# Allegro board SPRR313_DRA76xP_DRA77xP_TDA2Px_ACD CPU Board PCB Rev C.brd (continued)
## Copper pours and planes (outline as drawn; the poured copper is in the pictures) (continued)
VBUS_USB1 on L12-SIGNAL: 35.69,169.67 42.42,169.67 44.96,172.21 44.96,179.2 44.58,179.58 0.64,179.58 0.64,85.47 5.21,85.47 8.13,88.39 8.13,91.31 5.08,94.36 5.08,160.02 4.7,160.4 4.7,162.81 7.87,165.99 12.45,165.99 15.11,163.32 29.34,163.32
VBUS_USB2 on TOP: 35.69,167.77 35.43,167.51 35.43,165.48 35.69,165.23 37.72,165.23 37.97,165.48 37.97,166.88 37.08,167.77
VBUS_USB2 on L12-SIGNAL: 81.79,179.32 46.99,179.32 46.99,172.97 43.05,169.04 36.58,169.04 35.05,167.51 35.05,165.23 36.7,163.58 61.59,163.58 66.55,168.53 77.34,168.53 81.79,172.97
VCC_1V1USB on TOP: 45.09,114.3 47.88,114.3 48.26,114.68 48.26,115.95 48.01,116.2 45.59,116.2 44.96,115.57 44.96,114.43
VCC_1V1USB on L3-SIGNAL: 44.7,113.79 53.85,113.79 58.29,118.24 58.29,124.84 56.01,127.13 47.62,127.13 45.47,124.97 45.47,121.16 44.07,119.76 44.07,114.43
VCC_1V1VIDEO on TOP: 45.72,111.25 46.23,111.25 46.74,111.76 46.74,113.67 46.48,113.92 45.34,113.92 44.96,113.54 44.96,112.01
VCC_1V1VIDEO on BOTTOM: 31.62,103.5 31.37,103.5 31.37,104.65 31.75,105.03 31.75,110.36 32.13,110.74 33.4,110.74 34.42,109.73 34.42,105.16 33.15,103.89 32.13,103.89 32.13,103.5 31.88,103.5 31.88,104.14 31.62,104.14
VCC_1V1VIDEO on L3-SIGNAL: 31.37,103.89 31.37,112.78 34.92,116.33 34.92,126.87 34.54,127.25 24.77,127.25 23.11,125.6 18.54,125.6 17.53,126.62 17.53,131.7 19.56,133.73 34.67,133.73 40.13,128.27 40.13,108.84 34.67,103.38 31.88,103.38
VCC_1V1VIDEO on L5-SIGNAL: 31.37,113.54 45.34,113.54 46.61,112.27 46.61,105.79 42.8,101.98 32.51,101.98 30.1,104.39 30.1,112.27
VCC_CSI2_IO on L7-SIGNAL: 26.67,40.39 26.67,32.13 19.81,25.27 17.78,25.27 16.76,26.29 16.76,31.62 22.61,37.47 22.61,39.88 23.62,40.89 26.16,40.89
VCC_VTERM on L12-SIGNAL: 36.07,122.81 36.07,116.59 36.58,116.08 38.35,116.08 39.37,117.09 39.37,123.06 38.86,123.57 36.83,123.57
VDD18_DISP1 on L7-SIGNAL: 18.16,113.92 34.16,113.92 37.08,116.84 37.08,127.51 33.53,131.06 19.3,131.06 15.24,127 15.24,116.84
VDD_CDCEL925 on TOP: 50.55,51.69 50.55,48.01 50.93,47.62 50.93,46.86 50.67,46.61 47.62,46.61 46.48,47.75 46.48,53.34 47.12,53.98 48.01,53.98 48.64,53.34 48.64,52.45 49.02,52.07 50.16,52.07
VDD_CDCM9102 on L14-SIGNAL: 33.27,153.42 32.89,153.8 30.61,153.8 27.18,150.37 27.18,146.05 27.81,145.41 32,145.41 33.27,146.69
VDD_CORE_APM on TOP: 173.86,74.8 173.1,75.56 173.1,79.76 173.74,80.39 173.74,81.53 178.69,81.53 178.82,81.41 178.82,79.28 178.17,78.63 178.17,71.93 177.23,70.99 173.86,70.99
VDD_CORE_AVS on TOP: 178.69,82.04 175.01,82.04 175.01,84.07 178.69,84.07
VDD_CORE_AVS on L8-PWR1: 87.63,51.28 88.9,51.28 89.66,50.52 93.34,50.52 94.11,51.28 94.49,51.28 94.49,55.98 95,55.98 95.12,56.11 96.14,56.11 96.9,55.35 97.66,55.35 97.79,55.47 97.79,56.87 97.16,57.51 96.39,57.51 95.76,56.87 94.49,56.87 94.49,61.32 95.12,61.95 96.27,61.95 97.16,61.06 97.66,61.06 98.3,61.7 98.3,62.2 98.93,62.84 99.57,62.84 105.49,68.76 105.49,69.47 107.38,71.37 112.52,71.37 112.52,71.36 156.97,71.36 156.98,71.37 157.35,71.37 158.62,72.64 160.4,72.64 160.78,73.03 168.66,73.03 169.8,71.88 177.55,71.88 178.69,73.03 178.69,83.82 177.8,84.71 103.78,84.71 92.58,73.51 92.58,68.05 91.06,66.52 91.06,62.97 90.3,62.2 89.03,62.2 89,62.23 88.14,62.23 87.76,61.85 87.76,57.28 89.66,57.28 89.66,55.37 89.15,54.86 89.15,54.61 89.28,54.48 89.28,53.7 89.03,53.44 87.63,53.44
VDD_CORE_AVS on L12-SIGNAL: 85.72,48.87 85.72,52.58 90.04,56.9 90.04,60.43 95.12,60.43 96.14,59.41 96.14,49.12 95.89,48.87
VDD_CORE_SW3 on TOP: 166.75,72.01 168.4,72.01 168.53,72.14 169.04,72.14 170.05,71.12 172.34,71.12 172.34,73.91 168.28,73.91 167.89,73.53 167.89,72.52 167.77,72.39 166.75,72.39
VDD_DSPEVE_APM on TOP: 149.1,61.21 149.1,78.17 150.43,79.5 154.18,79.5 154.18,69.47 154.43,69.22 154.43,61.47 153.92,60.96 149.35,60.96
VDD_DSPEVE_AVS on TOP: 148.84,65.28 146.81,65.28 146.81,69.22 148.84,69.22
VDD_DSPEVE_AVS on L3-SIGNAL: 94.74,57 95.5,57 95.52,57.01 95.63,56.9 98.78,56.9 99.19,56.49 147.07,56.49 149.22,58.65 149.22,65.84 149.19,65.87 149.19,68.24 149.16,68.26 149.16,69.79 148.08,70.87 141.05,70.87 139.95,69.77 97.71,69.77 94.61,66.67 94.61,57.12
VDD_DSPEVE_AVS on L8-PWR1: 94.74,57 95.5,57 96.52,58.01 97.66,58.01 99.19,56.49 116.08,56.49 117.75,58.17 139.95,58.17 140.84,59.05 143.89,59.05 146.18,61.34 149.22,61.34 149.22,69.72 149.1,69.85 108.71,69.85 104.78,65.91 104.78,65.02 103.75,64 101.73,63.98 99.69,61.95 99.19,61.95 98.04,60.81 96.9,60.81 96.27,61.44 95,61.44 94.61,61.06 94.61,57.12
VDD_DSPEVE_SW1 on TOP: 160.53,69.85 155.45,69.85 154.81,69.22 154.81,66.04 155.07,65.79 157.35,65.79 157.86,66.29 157.86,68.2 159.13,69.47 159.64,69.47 159.77,69.6 160.53,69.6
VDD_DSPEVE_SW2 on TOP: 160.53,70.1 155.57,70.1 154.81,70.87 154.81,73.91 155.07,74.17 157.35,74.17 158.37,73.15 158.37,70.87 158.62,70.61 158.75,70.61 158.88,70.48 159.51,70.48 159.64,70.36 160.53,70.36
VDD_GPU_APM on TOP: 135.51,68.58 134.87,67.94 134.87,65.79 137.16,65.79 137.41,66.04 137.67,66.04 137.92,65.79 140.34,65.79 140.34,67.82 139.57,68.58 139.57,70.61 139.19,70.99 135.89,70.99 135.51,70.61
VDD_GPU_AVS on TOP: 135.89,71.25 139.19,71.25 139.19,73.66 138.94,73.91 136.14,73.91 135.89,73.66
VDD_GPU_AVS on L3-SIGNAL: 89.03,56.62 93.57,56.62 94.11,57.15 94.11,67.06 97.41,70.36 139.45,70.36 141.86,72.77 141.86,78.74 137.57,83.03 96.65,83.03 96.52,83.16 88.52,83.16 82.3,76.94 82.3,59.18 84.84,56.64 89.03,56.64
VDD_GPU_AVS on L9-PWR2: 89.03,56.62 90.93,56.62 91.19,56.87 91.19,57.89 91.88,58.59 93.15,58.59 93.34,58.78 93.34,61.32 93.22,61.44 93.22,61.57 92.08,62.71 92.08,67.03 95,69.95 95,70.48 96.62,72.11 135.89,72.11 135.89,72.14 139.19,72.14 139.57,72.52 139.57,78.11 138.81,78.87 136.37,78.87 131.93,83.31 97.41,83.31 97.4,83.3 91.55,83.3 91.29,83.57 82.17,83.57 77.09,78.49 77.09,62.48 77.62,61.95 87,61.95 87.5,61.44 87.5,60.81 88.52,59.79 88.52,59.28 89.03,58.78
VDD_GPU_SW2 on TOP: 134.87,64.64 134.87,63.75 135.13,63.5 136.53,63.5 136.91,63.12 136.91,60.71 137.16,60.71 137.16,64.64
VDD_GPU_SW3 on TOP: 140.21,64.64 140.21,63.75 139.95,63.5 138.56,63.5 138.18,63.12 138.18,60.71 137.92,60.71 137.92,64.64
VDD_IVA_APM on TOP: 161.29,83.44 161.67,83.82 169.8,83.82 170.43,83.19 170.43,80.52 169.67,79.76 165.48,79.76 165.23,79.5 161.93,79.5 161.29,80.14
VDD_IVA_AVS on TOP: 165.35,84.2 162.18,84.2 162.18,86.23 165.35,86.23
VDD_IVA_AVS on L9-PWR2: 89.79,53.57 89.28,53.57 88.93,53.21 72.26,53.21 67.69,57.78 67.69,88.9 72.39,93.6 153.54,93.6 159,88.14 160.91,88.14 162.43,86.61 162.43,84.07 163.32,83.19 165.74,83.19 167,84.45 167,90.93 158.62,99.31 62.23,99.31 55.88,92.96 55.88,47.75 78.49,47.75 79.25,48.51 89.92,48.51 90.93,49.53 90.93,52.45 90.58,52.81 90.55,52.81
VDD_IVA_SW4 on TOP: 163.32,73.15 163.32,74.68 161.42,76.58 161.42,78.74 161.8,79.12 164.47,79.12 164.97,78.61 164.97,76.2 163.7,74.93 163.7,74.04 163.58,73.91 163.58,73.15
VDD_MPU_APM on TOP: 135.51,51.56 134.87,52.2 134.87,54.36 137.16,54.36 137.41,54.1 137.67,54.1 137.92,54.36 140.34,54.36 140.34,52.32 139.57,51.56 139.57,49.53 139.19,49.15 135.89,49.15 135.51,49.53
VDD_MPU_AVS on TOP: 135.89,48.9 139.19,48.9 139.19,46.48 138.94,46.23 136.14,46.23 135.89,46.48
VDD_MPU_AVS on L3-SIGNAL: 104.27,55.16 104.05,55.37 98.3,55.37 97.41,56.26 92.08,56.26 91.44,55.63 91.44,42.93 93.85,40.51 137.41,40.51 140.21,43.31 140.21,50.55 139.45,51.31 139.26,51.31 139.26,51.37 135.47,55.16
VDD_MPU_AVS on L8-PWR1: 94.74,51.28 97.05,51.28 101.73,46.61 103,46.61 103.25,46.35 106.3,46.35 107.95,44.7 116.33,44.7 116.4,44.77 117.03,44.77 117.47,45.21 121.79,45.21 122.43,44.58 125.86,44.58 126.36,45.09 127.76,45.09 128.4,44.45 134.37,44.45 135,45.09 136.53,45.09 136.91,44.7 137.54,44.7 139.57,46.74 139.57,49.28 139.19,49.66 139.19,50.55 139.7,51.05 139.7,54.48 139.03,55.16 104.08,55.16 104.01,55.09 97.92,55.09 97.79,54.97 96.9,54.97 96.01,55.85 95.25,55.85 94.74,55.35
VDD_MPU_SW0 on TOP: 134.87,55.5 134.87,56.39 135.13,56.64 136.53,56.64 136.91,57.02 136.91,59.44 137.16,59.44 137.16,55.5
VDD_MPU_SW1 on TOP: 140.21,55.5 140.21,56.39 139.95,56.64 138.56,56.64 138.18,57.02 138.18,59.44 137.92,59.44 137.92,55.5
VDD_SDIO_APM on TOP: 177.8,70.74 177.8,67.94 175.64,67.94 174.88,68.71 174.88,70.1 175.51,70.74
VDD_SDIO_APM on L7-SIGNAL: 174.62,70.61 174.62,68.33 175.77,67.18 181.61,67.18 183.26,65.53 189.23,65.53 189.99,66.29 189.99,70.48 188.09,72.39 179.71,72.39 179.07,71.75 175.77,71.75
VDD_SDIO_DV on TOP: 178.18,67.94 178.18,70.74 180.21,70.74 180.21,67.94
VDD_SDIO_DV on L8-PWR1: 88.52,62.59 90.3,62.59 90.68,62.97 90.68,66.65 91.95,67.92 91.95,73.79 92.08,73.79 103.38,85.09 178.31,85.09 179.2,84.2 179.2,71.75 178.56,71.12 178.56,68.58 179.45,67.69 182.12,67.69 183.07,68.64 183.07,84.65 179.58,88.14 99.34,88.14 87.76,76.56 87.76,63.35
VDD_SDIO_DV on L10-SIGNAL: 130.43,154.31 142.24,154.31 147.32,159.38 209.04,159.38 215.39,153.03 215.39,91.06 210.57,86.23 210.57,69.85 220.22,69.85 220.22,164.85 216.66,168.4 130.3,168.4 126.75,164.85 126.75,157.99
VDD_SDIO_DV on L12-SIGNAL: 178.18,70.87 178.18,66.04 180.09,64.14 209.93,64.14 211.58,65.79 211.58,71.75 210.57,72.77 180.09,72.77
VDDA_CDCM9102 on L14-SIGNAL: 21.21,148.72 21.21,151.76 20.7,152.27 20.7,154.31 22.35,155.96 26.8,155.96 28.19,154.56 28.19,152.02 27.43,151.26 23.62,151.26 22.99,150.62 22.99,148.84 22.61,148.46 21.46,148.46
VDDHA_DISP1 on L10-SIGNAL: 31.88,127 31.88,119.25 33.15,117.98 35.69,117.98 37.08,119.38 37.08,127.89 35.81,129.16 34.04,129.16
VDDHS_DISP1 on L14-SIGNAL: 21.59,127.51 21.59,117.86 22.48,116.97 27.56,116.97 27.94,117.35 27.94,125.35 25.02,128.27 22.35,128.27
VDDI_MMC2 on TOP: 146.05,133.22 146.43,133.22 146.86,133.65 146.86,134.04 146.94,134.11 146.94,134.75 145.92,133.73 145.92,133.35
VDDL_DISP1 on L14-SIGNAL: 26.04,129.41 26.04,128.14 28.45,125.73 28.45,117.47 27.94,116.97 27.94,116.46 28.45,115.95 30.48,115.95 31.88,117.35 31.88,127.76 29.59,130.05 26.67,130.05
VDDR_APM on BOTTOM: 142.37,25.91 137.41,30.86 137.41,34.92 139.83,37.34 139.83,38.48 139.45,38.86 137.16,38.86 137.16,42.55 137.54,42.93 141.6,42.93 143.13,41.4 143.13,28.45 143.51,28.07 145.03,28.07 145.41,28.45 145.41,29.08 145.8,29.46 146.05,29.46 147.96,27.56 147.96,25.78 147.7,25.78 147.7,26.8 146.43,26.8 146.3,26.92 143.51,26.92 143.51,19.05 143.76,18.8 146.18,18.8 147.7,17.27 152.15,17.27 152.53,17.65 152.53,18.29 152.91,18.67 155.07,18.67 155.19,18.54 155.19,15.37 154.31,14.48 142.75,14.48 142.37,14.86
VDDR_MEM_1V35 on BOTTOM: 142.24,13.97 145.41,13.97 145.41,11.94 142.24,11.94
VDDR_MEM_1V35 on L8-PWR1: 55.24,10.79 55.24,33.4 55.26,33.39 140.73,33.39 141.48,32.64 141.48,29.72 140.08,29.72 140.08,25.91 146.3,25.91 146.3,11.68 145.41,10.79
VDDR_MEM_1V35 on L9-PWR2: 56.65,33.39 131.71,33.39 135.51,29.59 135.51,10.79 56.65,10.79
VDDR_SOC_1V35 on BOTTOM: 132.33,42.16 132.33,38.73 130.3,38.73 130.3,42.16
VDDR_SOC_1V35 on L8-PWR1: 88.77,51.03 89.66,50.14 93.22,50.14 94.11,51.03 96.14,51.03 97.65,49.52 97.65,48.4 102.36,43.69 131.7,43.69 131.7,33.78 68.83,33.78 68.83,42.8 77.88,42.8 86.11,51.03
VDDR_SOC_1V35 on L9-PWR2: 125.35,33.78 68.83,33.78 68.83,42.29 103.12,42.29 104.52,40.89 125.35,40.89
VDDR_SOC_APM on BOTTOM: 135.76,38.86 135.76,42.42 135.13,43.05 133.48,43.05 132.84,42.42 132.84,39.12 133.1,38.86
VDDR_SOC_VREFSTL on BOTTOM: 149.73,25.78 150.75,25.78 150.88,25.91 150.88,26.54 152.15,27.81 152.65,27.81 152.91,28.07 152.91,29.21 152.78,29.34 151.76,29.34 151.76,28.7 149.73,26.67
VDDR_SOC_VREFSTL on L7-SIGNAL: 95.89,50.16 95.5,50.55 94.23,50.55 93.34,49.66 93.34,42.93 92.58,42.16 88.9,42.16 87.76,43.31 87.76,49.4 86.61,50.55 85.85,50.55 85.22,49.91 85.22,44.7 82.93,42.42 75.82,42.42 74.8,41.4 74.8,40.51 76.39,38.93 105.85,38.93 114.05,30.73 141.35,30.73 142.88,29.21 145.54,29.21 148.97,25.78 150.37,25.78 151.38,26.8 151.38,28.32 145.8,33.91 116.2,33.91 107.89,42.23 98.11,42.23 95.89,44.45
VDDR_VREFSTL on L7-SIGNAL: 63.75,22.96 66.8,19.91 69.34,19.91 72.39,22.96 76.07,22.96 81.03,18.01 85.09,18.01 86.74,19.66 86.74,21.69 87.76,22.71 89.79,22.71 92.08,20.42 106.55,20.42 106.91,20.07 109.75,20.07 109.75,20.04 110.36,19.43 133.48,19.43 134.94,20.89 134.94,24.57 137.67,27.3 140.97,27.3 141.73,28.07 141.73,29.84 141.35,30.23 136.4,30.23 132.02,25.84 132.02,23.05 131.95,22.99 125.22,22.99 125.22,25.4 124.71,25.91 123.95,25.91 123.44,25.4 123.44,22.35 119.63,22.35 119.63,25.53 119.38,25.78 118.49,25.78 117.98,25.27 117.98,22.48 117.73,22.23 111,22.23 110.49,22.73 110.49,25.15 110.11,25.53 108.71,25.53 108.33,25.15 108.33,22.23 93.45,22.23 90.17,25.5 85.72,25.5 84.71,24.49 84.71,20.93 83.82,20.04 82.3,20.04 76.83,25.5 72.01,25.5 68.71,22.2 67.18,22.2 63.88,25.5 61.59,25.5 61.59,25.53 59.94,25.53 59.94,23.37 60.35,22.96
VDDS_1V8 on TOP: 160.91,55.75 164.08,55.75 164.08,53.72 160.91,53.72
VDDS_1V8 on L5-SIGNAL: 111.89,75.18 111.89,75.06 111,74.17 111,69.34 111.12,69.22 113.79,69.22 113.79,74.8 113.41,75.18
VDDS_1V8 on L9-PWR2: 97.22,63.16 99.44,65.38 101.47,65.38 101.6,65.51 108.2,65.51 108.81,64.9 108.84,64.9 108.84,62.1 119.38,62.1 119.38,61.85 121.67,59.56 125.98,59.56 127.38,58.17 127.38,52.2 129.29,50.29 162.94,50.29 164.97,52.32 164.97,56.13 141.6,56.13 137.16,60.58 137.16,70.59 96.52,70.59 92.33,66.4 92.33,62.71 93.22,61.82 96.9,61.82 97.28,62.2 97.28,63.09
VDDS_1V8 on L14-SIGNAL: 87.76,50.65 95.25,50.65 96.52,49.38 98.3,49.38 98.81,49.89 98.81,56.24 100.08,57.51 100.08,61.95 100.06,61.96 100.06,62.88 99.06,63.88 92.71,63.88 92.33,63.5 91.82,63.5 91.82,63.47 86.49,63.47 85.85,62.84 85.85,52.55
VDDS_1V8_APM on TOP: 164.47,55.88 164.34,55.88 163.96,56.26 161.29,56.26 160.78,56.77 160.78,60.2 161.16,60.58 172.85,60.58 173.1,60.33 173.1,56.39 181.61,56.39 181.86,56.13 181.86,52.96 181.74,52.83 177.8,52.83 177.29,53.34 166.37,53.34 165.1,54.61 165.1,55.24
VDDS_1V8_SW5 on TOP: 164.72,60.96 164.72,63.63 165.74,64.64 165.74,66.93 166.12,66.93 166.12,65.91 167.77,64.26 167.77,60.96
VDDSHV11 on L5-SIGNAL: 105.16,62.1 105.16,74.3 107.95,77.09 111.12,77.09 112.01,76.2 112.01,75.56 109.22,72.77 109.22,63.5 107.19,61.47 105.79,61.47
VDDSHV11 on L9-PWR2: 97.54,61.19 99.57,61.19 100.46,62.08 107.95,62.08 108.46,62.59 108.46,64.62 107.92,65.15 99.85,65.15 98.42,63.73 98.17,63.73 97.54,63.09
VDDSHV_3V3 on BOTTOM: 144.27,94.23 147.45,94.23 147.45,92.2 144.27,92.2
VDDSHV_3V3 on L5-SIGNAL: 87.5,49.15 101.35,49.15 102.74,50.55 102.74,73.03 108.58,78.87 108.58,84.96 109.03,85.41 112.59,85.41 121.79,94.61 128.52,94.61 131.57,91.57 146.94,91.57 147.83,92.46 147.83,99.95 144.78,103 121.67,103 111.51,92.84 93.22,92.84 90.93,90.55 90.93,73.03 91.44,72.52 91.44,65.02 89.53,63.12 87.12,63.12 85.85,61.85 85.85,50.8
VDDSHV_3V3 on L8-PWR1: 92.33,90.42 92.84,89.92 95.5,89.92 97.54,91.95 147.32,91.95 147.32,96.14 92.33,96.14
VDDSHV_3V3 on L12-SIGNAL: 99.82,50.01 99.82,63.6 93.22,63.6 93.22,68.81 94.61,70.21 94.61,78.61 94.55,78.68 94.55,91.76 94.11,92.2 92.46,92.2 92.08,91.82 92.08,90.81 91.57,90.3 91.57,70.08 92.08,69.57 92.08,63.47 86.11,63.47 86.11,57.02 86.49,56.64 89.15,56.64 89.66,57.15 89.66,60.71 95.5,60.71 96.65,59.56 96.65,50.65 97.28,50.01
VIN_CONN on TOP: 187.2,178.69 175.77,178.69 175.77,165.74 177.29,164.21 193.42,164.21 194.06,164.85 194.06,171.83
VIN_CONN on BOTTOM: 187.2,178.69 175.51,178.69 175.51,167 178.18,164.34 192.79,164.34 193.8,165.35 193.8,172.09
VIN_CONN on L3-SIGNAL: 187.2,178.69 174.24,178.69 174.24,165.48 177.04,162.69 192.15,162.69 193.8,164.34 193.8,172.09
VIN_CONN on L5-SIGNAL: 187.2,178.69 174.12,178.69 174.12,165.48 176.53,163.07 191.77,163.07 193.42,164.72 193.42,172.47
VIN_CONN on L7-SIGNAL: 187.2,178.69 173.99,178.69 173.99,164.85 175.77,163.07 192.28,163.07 193.8,164.59 193.8,172.09
VIN_CONN on L8-PWR1: 173.99,168.15 177.93,164.21 193.42,164.21 193.93,164.72 193.93,179.58 174.12,179.58 173.99,179.45
VIN_CONN on L12-SIGNAL: 174.75,119.51 166.12,119.51 157.23,128.4 157.23,151 178.56,172.34 191.77,172.34 194.06,170.05 194.06,156.21 188.47,150.62 165.48,150.62 163.07,148.21 163.07,134.37 163.7,133.73 170.56,133.73 175.9,128.4 175.9,120.65
VIN_CONN on L14-SIGNAL: 187.2,178.69 173.48,178.69 173.48,165.99 176.4,163.07 194.06,163.07 194.06,171.83
(no net) on TOP: 0.64,10.79 0.64,179.58 220.22,179.58 220.22,10.79 ; 11 cut-outs
(no net) on BOTTOM: 0.64,10.79 0.64,179.58 220.22,179.58 220.22,10.79 ; 11 cut-outs
AIC_DRVDD3.3 on TOP: 182.63,36.2 180.97,36.2 180.85,36.32 177.42,36.32 177.42,38.23 178.05,38.86 181.23,38.86 182.88,37.21 182.88,36.45
LDOVRTC on L10-SIGNAL: 168.4,66.55 169.04,65.91 169.04,63.63 168.78,63.37 167.64,63.37 167.39,63.63 163.96,63.63 163.19,64.39 163.19,76.07 163.96,76.83 167.89,76.83 168.4,76.33
PHA on TOP: 174.5,122.81 174.12,122.43 157.48,122.43 157.48,132.33 161.8,132.33 162.31,132.84 162.31,134.11 166.62,134.11 166.62,133.6 170.43,133.6 170.43,134.11 174.5,134.11
PHA on L3-SIGNAL: 174.5,134.11 174.5,122.81 174.12,122.43 157.48,122.43 157.48,132.33 161.8,132.33 162.31,132.84 162.31,134.11
PHB on TOP: 194.31,121.41 194.31,132.33 189.74,132.33 189.48,132.59 189.48,134.11 183.13,134.11 183.13,133.6 180.09,133.6 180.09,134.11 176.02,134.11 176.02,122.81 176.4,122.43 177.93,122.43 178.94,121.41
PHB on L3-SIGNAL: 194.31,121.41 194.31,132.33 189.74,132.33 189.48,132.59 189.48,134.11 176.02,134.11 176.02,122.81 176.4,122.43 177.93,122.43 178.94,121.41
VDA_ABEPERMPU_F1V8 on L9-PWR2: 93.6,61.57 96.77,61.57 97.54,60.81 100.58,60.81 101.47,61.7 118.87,61.7 120.78,59.79 120.78,57.51 120.4,57.12 119.63,57.12 117.86,58.9 93.98,58.9 93.6,59.28
VDA_ABEPERMPU_F1V8 on L14-SIGNAL: 92.71,52.68 92.71,60.43 93.85,61.57 94.36,61.57 94.74,61.19 94.74,53.06 94.36,52.68
VDA_CSI_F1V8 on L8-PWR1: 88.89,54.34 89.03,54.2 89.03,53.95 88.9,53.82 87.76,53.82 87.38,54.2 87.25,54.2 87.12,54.33 87.12,55.98 68.73,55.98 68.71,56.01 68.71,72.77 73.91,72.77 73.91,61.91 77.34,58.48 79.82,58.48 80.77,57.53 81.41,57.53 82.04,56.9 89.28,56.9 89.28,55.37 88.89,54.98
VDA_DBGDSPEVE_F1V8 on L9-PWR2: 114.81,56.01 117.09,53.72 120.14,53.72 120.65,54.23 120.65,55.37 117.47,58.55 93.98,58.55 93.6,58.17 93.6,57.53 95.12,56.01
VDA_DDRGCOREVID_F1V8 on L9-PWR2: 91.44,57.4 91.44,55.37 93.85,52.96 93.85,52.2 93.98,52.07 112.78,52.07 114.68,50.16 120.14,50.16 120.4,50.42 120.4,53.21 120.14,53.47 116.84,53.47 114.55,55.75 95,55.75 93.22,57.53 91.57,57.53
VDA_GPUIVA_F1V8 on L9-PWR2: 91.19,56.13 91.19,55.37 93.6,52.93 93.6,51.79 112.65,51.79 115.44,49 115.44,46.71 115.06,46.33 111.4,46.33 109.22,48.51 91.69,48.51 91.69,52.3 89.92,54.08 88.27,54.08 88.01,54.33 88.01,56.13
VDA_HDMI_F1V8 on L9-PWR2: 87.38,53.82 85.47,53.82 85.41,53.89 82.99,53.89 82.98,53.9 72.85,53.9 68.71,58.04 68.71,67.94 69.22,68.45 70.1,68.45 70.61,67.94 70.61,59.69 74.19,56.11 80.77,56.11 80.77,56.13 87.35,56.13 87.38,56.11
VDA_OSC_F1V8 on L8-PWR1: 74.04,43.18 74.05,43.17 77.61,43.17 87.12,52.68 87.12,55.73 68.81,55.73 68.71,55.63 68.71,43.18
VDA_PCIE_F1V8 on L9-PWR2: 88.27,59.03 88.77,58.52 88.77,57.12 88.72,57.07 88.72,56.72 88.39,56.39 74.55,56.39 71.12,59.82 71.12,67.94 71.5,68.33 72.77,68.33 73.41,67.69 73.41,60.45 74.83,59.03
VDA_PHY1_1V8 on TOP: 155.57,84.58 152.4,84.58 152.4,86.61 155.57,86.61
VDA_PHY1_1V8 on L9-PWR2: 73.03,71.25 72.39,70.61 68.96,70.61 68.83,70.74 68.83,82.3 69.85,83.31 69.85,89.41 73.15,92.71 120.78,92.71 121.16,92.33 148.46,92.33 148.84,91.95 153.92,91.95 156.21,89.66 156.21,86.61 155.96,86.36 155.96,85.09 150.11,85.09 146.94,88.27 78.74,88.27 73.03,82.55
VDA_PHY1_APM on TOP: 153.29,79.88 154.43,79.88 155.45,78.87 156.97,78.87 157.86,77.98 157.86,75.82 159.51,74.17 160.78,74.17 161.04,74.42 161.04,75.18 160.78,75.44 159.89,75.44 158.88,76.45 158.88,79.12 155.57,82.42 155.57,83.82 155.19,84.2 155.07,84.2 155,84.14 154.94,84.2 152.53,84.2 152.15,83.82 152.15,81.03
VDA_PHY2_1V8 on TOP: 160.78,84.58 157.61,84.58 157.61,86.61 160.78,86.61
VDA_PHY2_1V8 on L9-PWR2: 156.34,86.23 156.34,84.71 149.86,84.71 146.81,87.76 78.74,87.76 73.41,82.42 73.41,71.12 72.52,70.23 68.96,70.23 68.96,68.83 76.45,68.83 76.71,69.09 76.71,78.61 82.04,83.95 91.82,83.95 92.08,83.69 132.21,83.69 136.65,79.25 157.86,79.25 161.29,82.68 161.29,86.23 160.53,87 157.1,87
VDA_PHY2_APM on TOP: 163.07,74.68 161.16,76.58 161.16,83.57 160.66,84.07 157.73,84.07 157.35,83.69 157.35,81.03 159.13,79.25 159.13,76.58 160.02,75.69 160.91,75.69 161.54,75.06 161.54,74.55 161.93,74.17 162.94,74.17 163.07,74.3
VDA_PLL_1V8 on TOP: 176.91,60.2 176.91,63.37 178.94,63.37 178.94,60.2
VDA_PLL_1V8 on L9-PWR2: 108.84,48.11 111.18,45.77 115.32,45.77 115.77,46.23 115.82,46.23 115.82,49.66 120.4,49.66 121.16,50.42 121.16,59.18 121.21,59.23 125.6,59.23 126.87,57.96 126.87,51.94 128.91,49.91 163.32,49.91 165.61,52.2 165.61,63.63 176.78,63.63 177.16,63.25 178.82,63.25 178.82,60.07 177.93,59.18 173.35,59.18 171.7,57.53 171.7,47.5 169.16,44.96 128.52,44.96 125.09,41.53 119,41.53 119,41.52 105.27,41.52 104.11,42.67 68.71,42.67 68.58,42.8 68.58,47.24 72.39,47.24 72.39,47.29 78.69,47.29 79.5,48.11
VDA_PLL_APM on TOP: 176.53,60.58 175.13,60.58 172.09,63.63 172.09,65.28 170.69,66.67 170.05,66.67 169.42,67.31 169.42,67.69 169.8,68.07 171.96,68.07 173.86,66.17 173.86,65.79 176.15,63.5 176.53,63.5
VDA_PLL_APM on L3-SIGNAL: 174.5,61.72 177.04,59.18 177.04,57.78 176.02,56.77 167.77,56.77 167.26,56.26 158.5,56.26 157.23,54.99 151.13,54.99 148.46,52.32 143.64,52.32 141.6,50.29 141.6,17.4 139.83,15.62 32.64,15.62 29.84,18.41 29.84,36.83 34.42,41.4 46.61,41.4 53.98,48.77 53.98,52.45 53.09,53.34 34.16,53.34 25.59,44.77 25.59,40.83 24.38,39.62 24.38,33.15 22.99,31.75 22.99,15.88 27.81,11.05 150.37,11.05 160.15,20.83 160.15,47.88 165.61,53.34 178.44,53.34 180.21,55.12 180.21,63.37 179.45,64.14 174.88,64.14 174.5,63.75
VDA_SATA_F1V8 on L8-PWR1: 86.82,58.72 86.77,58.67 83.82,58.67 80.14,62.36 80.14,72.77 74.3,72.77 74.3,62.1 77.53,58.86 80.07,58.86 81.17,57.77 81.66,57.77 82.03,57.4 87.38,57.4 87.38,58.17
VDA_USB_3V3 on TOP: 178.18,64.01 178.18,67.18 180.21,67.18 180.21,64.01
VDA_USB_3V3 on L8-PWR1: 84.07,58.9 82.92,60.06 82.92,60.07 80.39,62.6 80.39,82.93 86.66,89.2 95.58,89.2 97.94,91.57 182.37,91.57 186.31,87.63 186.31,66.04 183.51,63.25 179.45,63.25 178.69,64.01 178.69,67.06 178.94,67.31 182.5,67.31 183.51,68.33 183.51,77.85 183.48,77.89 183.48,85.05 179.96,88.57 99.06,88.57 87.25,76.76 87.25,59.54 86.61,58.9
VDA_USB_APM on TOP: 177.67,64.14 176.15,64.14 174.24,66.04 174.24,66.42 172.34,68.33 169.16,68.33 168.91,68.58 168.91,68.96 169.16,69.22 173.86,69.22 175.51,67.56 177.67,67.56
VDA_USB_F1V8 on L9-PWR2: 87,59.28 88.01,59.28 88.14,59.41 88.14,59.79 87.25,60.68 87.25,61.32 86.97,61.59 77.22,61.59 76.45,62.36 76.45,67.82 75.95,68.33 74.68,68.33 73.91,67.56 73.91,60.58 75.15,59.35 86.93,59.35
VDAC_3V3 on L3-SIGNAL: 175.51,52.7 176.53,51.69 176.53,50.67 177.55,49.66 186.06,49.66 186.31,49.4 186.31,48.77 185.17,47.62 185.17,34.92 183.39,33.15 182.12,33.15 181.61,33.66 181.61,43.81 180.34,45.09 172.72,45.09 170.94,46.86 169.04,46.86 166.5,44.32 164.08,44.32 162.31,46.1 162.31,49.28 165.74,52.7
VDISP1_12V0 on TOP: 6.86,140.21 4.32,140.21 3.94,139.83 3.94,137.92 4.45,137.41 6.22,137.41 6.86,138.05
VDISP1_12V0 on L3-SIGNAL: 0.76,141.73 0.76,129.79 2.67,127.89 10.67,127.89 11.94,129.16 11.94,135.89 11.05,136.78 11.05,138.81 8.13,141.73
VDISP2_12V0 on TOP: 211.33,149.22 211.33,152.15 210.82,152.65 209.04,152.65 208.53,152.15 208.53,149.86 209.17,149.22
VDISP2_12V0 on L3-SIGNAL: 159.51,164.34 174.37,164.34 176.78,161.93 208.28,161.93 214.5,155.7 214.5,151.89 211.2,148.59 171.07,148.59 158.62,161.04 158.62,163.45
VFTDI_3V3 on L5-SIGNAL: 172.97,168.53 172.97,165.35 175.77,162.56 195.33,162.56 204.85,172.09 209.42,172.09 209.93,171.58 209.93,164.72 203.2,157.99 170.69,157.99 163.58,165.1 163.58,167.89 164.85,169.16 172.34,169.16
VIO_1V8 on TOP: 182.37,52.83 182.37,56.01 184.4,56.01 184.4,52.83
VIO_1V8 on BOTTOM: 151.38,134.62 154.69,134.62 154.94,134.37 154.94,133.35 154.69,133.1 149.35,133.1 149.35,134.87 149.61,135.13 150.88,135.13
VIO_1V8 on L3-SIGNAL: 183.64,53.21 181.99,53.21 180.72,54.48 180.72,64.14 180.21,64.64 171.96,64.64 170.18,66.42 164.34,66.42 164.34,59.44 164.08,59.18 158.5,59.18 156.46,61.21 156.46,65.79 159.38,68.71 181.23,68.71 184.4,65.53 184.4,53.98
VIO_1V8 on L3-SIGNAL: 15.11,62.1 15.11,54.99 15.75,54.36 15.75,47.75 16.13,47.37 18.92,47.37 19.3,47.75 19.3,61.72 16.38,64.64 14.35,64.64 13.97,64.26 13.97,63.25
VIO_1V8 on L5-SIGNAL: 93.09,105.28 89.15,105.28 75.95,118.49 56.64,118.49 52.32,114.17 22.48,114.17 17.53,119.13 17.53,139.83 46.61,168.91 86.36,168.91 96.9,158.37 96.9,109.09
VIO_1V8 on L7-SIGNAL: 143.51,59.44 143.51,57.91 144.78,56.64 157.35,56.64 160.27,59.56 160.27,60.45 159.77,60.96 145.03,60.96
VIO_1V8 on L9-PWR2: 220.22,54.36 220.22,179.58 0.64,179.58 0.64,10.79 56.26,10.79 56.26,33.78 68.2,33.78 68.2,47.24 55.37,47.24 55.37,92.46 30.35,92.46 30.35,116.2 40.64,116.2 40.64,130.3 27.56,130.3 27.56,157.23 38.23,167.89 83.31,167.89 83.31,164.47 76.07,157.23 76.07,153.16 76.2,153.03 142.37,153.03 142.37,127.64 189.1,127.64 189.23,127.51 189.1,127.38 189.1,63.25 182.82,56.96 182.82,51.88 183.77,50.93 191.13,50.93 194.56,54.36
VIO_1V8 on L12-SIGNAL: 184.78,55.37 184.78,44.58 189.23,40.13 189.23,24.77 186.18,21.72 164.08,21.72 162.81,22.99 162.81,25.15 163.96,26.29 177.55,26.29 180.59,29.34 180.59,33.91 176.91,37.59 176.91,53.21 179.07,55.37 182.25,55.37 182.63,55.75 184.4,55.75
VIO_3V3 on TOP: 141.22,144.91 142.75,144.91 143.64,145.8 146.18,145.8 146.43,145.54 146.43,141.86 146.18,141.6 143.13,141.6 142.62,142.11 141.22,142.11 141.22,142.37 142.49,142.37 142.75,142.62 142.75,143.51 142.62,143.64 141.22,143.64 141.22,143.89 142.62,143.89 142.75,144.02 142.75,144.53 142.62,144.65 141.22,144.65
VIO_3V3 on TOP: 112.65,107.31 114.17,107.31 114.68,107.82 115.95,107.82 116.33,107.44 116.33,106.3 116.08,106.05 114.94,106.05 114.17,106.81 112.65,106.81 112.52,106.93 112.52,107.19
VIO_3V3 on BOTTOM: 149.35,132.84 153.8,132.84 153.8,131.83 153.29,131.32 153.29,130.43 153.03,130.18 152.4,130.18 151.76,130.81 150.24,130.81 149.99,131.06 149.99,131.83 149.35,132.46
VIO_3V3 on BOTTOM: 149.1,94.23 152.27,94.23 152.27,92.2 149.1,92.2
VIO_3V3 on BOTTOM: 177.29,26.16 177.29,22.99 177.55,22.73 179.2,22.73 179.58,23.11 179.58,25.91 178.69,25.91 178.44,26.16
VIO_3V3 on L7-SIGNAL: 134.49,92.71 146.69,92.71 147.32,93.34 151.89,93.34 152.27,92.96 152.27,90.93 151.51,90.17 147.83,90.17 145.8,88.14 135,88.14 133.6,89.53 133.6,91.82
VIO_3V3 on L8-PWR1: 0.64,179.58 0.64,10.79 54.86,10.79 54.86,33.78 68.33,33.78 68.33,73.15 79.76,73.15 79.88,73.28 79.88,83.06 86.36,89.53 91.82,89.53 91.95,89.66 91.95,96.52 147.7,96.52 147.7,91.95 182.5,91.95 186.69,87.76 186.69,65.79 183.51,62.61 178.05,62.61 178.05,69.34 177.93,69.47 149.73,69.47 149.73,58.55 147.19,56.01 140.34,56.01 140.34,45.97 138.05,43.69 132.21,43.69 132.21,33.78 140.97,33.78 141.92,32.83 141.92,29.53 141.99,29.46 141.86,29.34 140.46,29.34 140.46,26.29 146.69,26.29 146.69,10.79 220.22,10.79 220.22,179.58 194.94,179.58 194.31,178.94 194.31,164.59 193.55,163.83 177.67,163.83 173.61,167.89 173.61,179.58
VIO_3V3 on L10-SIGNAL: 123.95,75.31 121.41,77.85 120.65,77.85 120.14,78.36 120.14,78.87 120.4,79.12 137.16,79.12 140.46,75.82 148.59,75.82 149.35,76.58 149.35,85.09 149.1,85.34 148.08,85.34 146.94,84.2 142.37,88.77 142.37,92.08 140.59,93.85 135.64,93.85 133.73,91.95 133.73,90.81 135.13,89.41 138.68,89.41 140.34,87.76 140.34,84.33 138.81,82.8 137.41,82.8 135,85.22 129.67,85.22 127.13,87.76 109.35,87.76 107.95,86.36 107.95,74.55 109.86,72.64 123.44,72.64 123.95,73.15
VIO_3V3 on L12-SIGNAL: 121.54,49.15 121.54,47.24 121.92,46.86 123.57,46.86 123.83,46.61 123.83,45.72 123.44,45.34 114.05,45.34 112.65,43.94 112.65,42.16 113.16,41.66 115.19,41.66 117.86,38.99 123.32,38.99 123.7,38.61 125.86,38.61 129.41,35.05 132.84,35.05 137.29,39.5 151.38,39.5 152.4,38.48 158.62,38.48 159.89,39.75 159.89,42.55 159.26,43.18 134.49,43.18 131.32,40.01 129.16,40.01 128.78,40.39 128.78,42.55 129.79,43.56 129.79,48.64 129.54,48.9 127.64,48.9 127.57,48.83 123.63,48.83 122.94,49.53 121.92,49.53
VIO_3V3_SD on L12-SIGNAL: 121.92,157.61 139.06,157.61 139.45,157.99 139.45,163.32 137.67,165.1 125.86,165.1 120.78,160.02 120.78,158.75
VIO_3V3USB on L10-SIGNAL: 49.28,111.76 52.45,111.76 58.29,117.6 58.29,125.6 55.88,128.02 46.35,128.02 43.69,125.35 43.69,117.35
VIO_3V6 on TOP: 12.45,36.53 10.34,36.53 10.16,36.35 10.16,32.77 9.4,32 5.33,32 4.32,33.02 2.92,33.02 2.54,32.64 2.54,31.75 2.67,31.62 2.67,30.73 3.05,30.35 3.05,29.21 1.27,29.21 0.89,29.59 0.89,34.04 1.4,34.54 2.67,34.54 2.92,34.8 4.7,34.8 4.95,35.05 4.95,36.2 6.6,37.85 9.98,37.85 10.31,37.52 12.45,37.52 12.45,37.16 10.31,37.16 10.31,36.88 12.45,36.88
VIO_3V6 on L3-SIGNAL: 6.6,29.21 10.29,32.89 10.29,37.72 10.03,37.97 6.48,37.97 3.43,34.92 1.4,34.92 0.76,34.29 0.76,29.59 1.14,29.21
VLIM_12V0 on TOP: 180.72,155.7 180.72,149.99 187.96,149.99 188.85,150.88 191.77,150.88 192.66,151.76 192.66,156.21 192.28,156.59 191.77,156.59 190.88,155.7
VPHY_1V1 on BOTTOM: 82.17,162.94 82.42,162.94 82.42,161.8 82.04,161.42 82.04,156.08 81.66,155.7 80.26,155.7 79.76,156.21 79.76,161.67 80.64,162.56 81.66,162.56 81.66,162.94 81.92,162.94 81.92,162.31 82.17,162.31
VPHY_1V1 on L12-SIGNAL: 79.5,161.8 79.5,153.92 91.19,142.24 91.19,132.84 90.36,132.02 90.36,129.73 96.65,123.44 101.35,123.44 105.92,128.02 105.92,129.92 104.52,131.32 104.52,147.45 89.15,162.81 80.52,162.81
VPHY_2V5 on BOTTOM: 77.34,148.34 77.6,148.34 77.6,147.19 77.22,146.81 77.22,141.48 76.83,141.1 75.56,141.1 74.55,142.11 74.55,146.69 75.82,147.96 76.83,147.96 76.83,148.34 77.09,148.34 77.09,147.7 77.34,147.7
VPHY_2V5 on L10-SIGNAL: 74.55,148.34 74.55,141.48 75.18,140.84 83.69,140.84 88.9,135.64 103.38,135.64 105.54,137.79 105.54,152.53 98.04,160.02 88.77,160.02 78.99,150.24 76.45,150.24
VPIN_B01_3V3 on TOP: 136.65,59.44 136.65,57.15 136.4,56.9 134.87,56.9 134.62,56.64 134.62,55.63 134.37,55.37 132.33,55.37 131.95,55.75 131.95,57.15 132.46,57.66 135.13,57.66 135.25,57.53 136.4,57.53 136.4,59.44
VPIN_B01_3V3 on TOP: 138.43,59.44 138.43,57.15 138.68,56.9 140.21,56.9 140.46,56.64 140.46,55.63 140.72,55.37 144.27,55.37 144.65,55.75 144.65,57.28 144.27,57.66 139.95,57.66 139.83,57.53 138.68,57.53 138.68,59.44
VPIN_B01_3V3 on L12-SIGNAL: 143.51,55.24 143.51,57.78 142.88,58.42 132.59,58.42 131.32,57.15 131.32,55.12 133.22,53.21 141.48,53.21
VPIN_B23_3V3 on TOP: 138.43,60.71 138.43,62.99 138.68,63.25 140.21,63.25 140.46,63.5 140.46,64.52 140.72,64.77 143.89,64.77 144.4,64.26 144.4,63.12 143.76,62.48 139.95,62.48 139.83,62.61 138.68,62.61 138.68,60.71
VPIN_B23_3V3 on TOP: 136.65,60.71 136.65,62.99 136.4,63.25 134.87,63.25 134.62,63.5 134.62,64.52 134.37,64.77 132.33,64.77 131.95,64.39 131.95,62.99 132.46,62.48 135.13,62.48 135.25,62.61 136.4,62.61 136.4,60.71
VPIN_B23_3V3 on L12-SIGNAL: 132.33,61.85 142.62,61.85 143.64,62.87 143.64,65.28 141.86,67.06 133.1,67.06 131.7,65.66 131.7,62.48
VPIN_LDO_3V3 on L5-SIGNAL: 160.91,75.69 160.91,71.25 171.2,60.96 173.86,60.96 174.37,61.47 174.37,64.9 168.28,70.99 167.39,70.99 165.86,72.52 165.86,74.68 164.47,76.07 161.29,76.07
VPIN_LDO_5V0 on L7-SIGNAL: 171.32,68.07 175.51,72.26 178.75,72.26 179.77,73.28 179.77,75.37 178.31,76.83 168.91,76.83 167,74.93 167,68.58 167.51,68.07
VPIN_S3_3V3 on L5-SIGNAL: 167.64,71.37 168.53,71.37 172.34,75.18 179.58,75.18 180.47,76.07 180.47,78.23 179.96,78.74 169.8,78.74 166.37,75.31 166.37,72.64
VPIN_S4_3V3 on L3-SIGNAL: 163.45,73.79 167,73.79 172.34,79.12 172.34,80.39 172.09,80.64 167,80.64 163.45,77.09
VPIN_S5_3V3 on L3-SIGNAL: 169.67,66.17 164.59,66.17 164.59,60.45 167.77,57.28 175.9,57.28 176.66,58.04 176.66,59.18
VPIN_S12_3V3 on TOP: 152.78,59.05 152.78,58.04 153.03,57.78 154.69,57.78 155.19,58.29 155.19,58.93 154.69,59.44 153.16,59.44
VPIN_S12_3V3 on L5-SIGNAL: 160.4,62.1 156.21,57.91 153.92,57.91 153.67,58.17 153.67,63.5 156.72,66.55 156.72,69.09 158.88,71.25 160.02,71.25 160.4,70.87
VPO_DDR_SW on BOTTOM: 147.07,23.24 147.07,22.73 147.96,22.73 147.96,21.72 147.7,21.46 146.56,21.46 146.18,21.08 146.18,19.68 144.15,19.68 144.15,21.84 144.4,22.1 145.16,22.1 146.3,23.24
VPO_DDR_VTT on BOTTOM: 148.46,25.78 148.21,25.78 148.21,27.69 146.18,29.72 146.18,32.13 148.34,32.13 148.84,31.62 148.78,31.56 148.78,27.56 148.46,27.24
VPOC2_12V0 on L14-SIGNAL: 150.5,176.78 150.5,166.12 154.56,162.05 156.97,162.05 157.48,162.56 157.48,175.51 155.32,177.67 151.38,177.67
VSW_3V3_APM on BOTTOM: 147.7,99.06 147.7,98.3 148.46,97.54 151.13,97.54 152.02,96.65 152.02,94.74 145.03,94.74 144.15,95.63 144.15,98.3 144.91,99.06
VSYS_3V3 on TOP: 139.19,60.2 143.38,60.2 144.15,59.44 144.15,58.42 145.03,57.53 145.03,55.63 145.41,55.24 149.48,55.24 152.27,58.04 152.27,59.31 152.53,59.56 152.53,60.33 152.27,60.58 149.1,60.58 148.84,60.83 148.84,64.9 146.69,64.9 146.43,65.15 145.16,65.15 144.78,64.77 144.78,62.74 144.27,62.23 141.48,62.23 141.1,61.85 141.1,60.83 140.72,60.45 139.19,60.45
VSYS_3V3 on TOP: 164.47,100.33 164.47,96.27 164.97,95.76 167,95.76 167.26,96.01 167.26,100.71 164.85,100.71
VSYS_3V3 on BOTTOM: 148.08,22.73 148.08,21.59 147.19,20.7 147.19,18.03 147.57,17.65 148.84,17.65 149.1,17.91 149.1,20.95 148.97,21.08 148.97,22.73
VSYS_3V3 on BOTTOM: 147.7,100.46 147.7,101.85 147.32,102.23 147.32,103.12 147.19,103.25 145.67,103.25 145.03,102.62 145.03,99.44 146.69,99.44 146.69,100.46
VSYS_3V3 on L5-SIGNAL: 163.07,101.47 169.8,101.47 171.45,103.12 173.48,103.12 175.64,105.28 178.69,105.28 179.58,104.39 179.58,101.85 179.96,101.47 216.92,101.47 219.96,98.42 219.96,11.05 219.84,10.92 138.43,10.92 137.03,12.32 137.03,50.29 143.64,56.9 172.72,56.9 181.86,66.04 181.86,78.61 180.34,80.14 162.81,80.14 161.29,81.66 161.29,99.69
VSYS_3V3 on L5-SIGNAL: 167.39,160.66 171.2,156.84 180.47,156.84 189.48,147.83 189.48,143.13 188.72,142.37 176.4,142.37 160.91,157.86 160.91,159 162.56,160.66
VSYS_3V3 on L9-PWR2: 82.68,167.39 82.68,164.47 75.69,157.48 75.69,152.65 141.99,152.65 141.99,127.25 188.59,127.25 188.59,63.5 182.37,57.28 182.37,51.44 183.51,50.29 191.26,50.29 194.94,53.98 220.09,53.98 220.22,53.85 220.22,10.79 137.67,10.79 136.14,12.32 136.14,29.72 132.08,33.78 125.98,33.78 125.98,41.53 128.91,44.45 169.29,44.45 172.09,47.24 172.09,57.4 173.48,58.8 178.44,58.8 179.32,59.69 179.32,63.5 177.42,63.5 176.78,64.14 164.97,64.14 164.97,57.15 164.59,56.77 142.11,56.77 138.05,60.83 138.05,70.36 140.08,72.39 140.08,78.36 140.34,78.61 158.24,78.61 162.18,82.55 163.83,82.55 163.89,82.49 165.93,82.49 167.64,84.2 167.64,91.06 159,99.69 61.98,99.69 55.24,92.96 30.73,92.96 30.73,115.7 30.86,115.82 41.02,115.82 41.02,130.68 27.94,130.68 27.94,156.97 38.35,167.39
VSYS_3V3 on L12-SIGNAL: 147.45,54.86 148.59,56.01 163.45,56.01 163.96,55.5 168.28,55.5 170.43,57.66 172.34,57.66 174.24,55.75 181.86,55.75 182.5,56.39 182.5,59.56 180.47,61.59 148.21,61.59 143.89,57.28 143.89,54.86 141.6,52.58 136.78,52.58 135.13,50.93 135.13,49.15 135.51,48.77 145.8,48.77 147.45,50.42
VSYS_3V3 on L12-SIGNAL: 170.43,81.79 200.53,81.79 218.57,99.82 218.57,138.68 209.55,147.7 191.9,147.7 188.21,144.02 188.21,113.92 189.23,112.9 189.23,92.96 186.82,90.55 180.47,90.55 179.58,91.44 179.58,94.11 178.18,95.5 152.91,95.5 146.43,101.98 144.65,101.98 143.89,101.22 143.89,87.76 146.3,85.34 153.42,85.34 155.7,83.06 169.16,83.06
VSYS_3V3_APM on TOP: 168.4,109.98 168.4,107.19 166.37,105.16 163.07,105.16 162.43,104.52 162.43,101.85 164.08,100.2 164.08,96.77 163.58,96.27 162.43,96.27 162.31,96.39 150.62,96.39 149.61,97.41 149.61,101.09 147.64,103.06 147.64,104.46 146.94,105.16 145.54,105.16 145.03,105.66 145.03,124.08 145.54,124.59 155.7,124.59 156.21,124.08 156.21,114.68 160.4,110.49 167.89,110.49
VSYS_3V3_APM on BOTTOM: 152.53,96.9 152.15,97.28 152.15,101.22 148.59,104.78 148.59,124.59 155.7,124.59 156.21,124.08 156.21,114.68 160.4,110.49 167,110.49 167.51,109.98 167.51,105.54 167.13,105.16 163.07,105.16 160.85,102.93 160.85,99.89 160.91,99.82 160.91,97.28 160.53,96.9
VSYS_3V3_APM on L3-SIGNAL: 168.4,109.98 168.4,106.43 167.13,105.16 163.07,105.16 162.43,104.52 162.43,101.35 163.07,100.71 163.07,98.04 161.93,96.9 152.02,96.9 150.62,98.3 150.62,101.47 145.41,106.68 145.41,112.65 145.03,113.03 145.03,120.52 148.08,123.57 155.45,123.57 156.21,122.81 156.21,114.68 160.4,110.49 167.89,110.49
VSYS_3V3_APM on L12-SIGNAL: 171.83,100.46 171.83,112.01 160.53,123.32 145.67,123.32 145.03,122.68 145.03,107.06 148.59,107.06 152.53,103.12 152.53,99.57 151.83,98.87 151.83,97.09 152.78,96.14 167.51,96.14
VSYS_5V0 on TOP: 182.12,91.82 182.12,95.89 179.96,95.89 179.96,91.82
VSYS_5V0 on BOTTOM: 179.58,29.34 179.58,32.26 179.32,32.51 177.67,32.51 177.29,32.13 177.29,29.34
VSYS_5V0 on L10-SIGNAL: 219.46,179.2 219.96,178.69 219.96,173.61 215.39,169.04 130.18,169.04 119.76,158.62 119.76,152.02 119.13,151.38 108.84,151.38 99.25,160.97 88.33,160.97 78.61,151.26 70.36,151.26 68.45,153.16 59.18,153.16 52.45,146.43 38.48,146.43 32.64,140.59 32.64,130.81 31.11,129.29 31.11,122.56 23.88,115.32 23.88,109.98 31.11,102.74 31.11,99.57 25.65,94.11 9.02,94.11 6.48,91.57 6.48,25.27 5.97,24.77 1.52,24.77 1.14,25.15 1.14,179.2
VSYS_5V0 on L12-SIGNAL: 138.56,33.4 148.08,33.4 154.56,26.92 177.42,26.92 180.09,29.59 180.09,33.4 177.16,36.32 165.86,36.32 165.74,36.2 153.8,36.2 151.38,38.61 145.54,38.61 145.03,39.12 137.79,39.12 137.03,38.35 137.03,34.92
VSYS_5V0 on L12-SIGNAL: 151.76,99.44 149.73,99.44 146.69,102.49 125.73,102.49 123.32,100.08 123.32,96.01 122.24,94.93 122.24,92.14 120.4,90.3 108.08,90.3 107.06,91.31 107.06,92.58 107.95,93.47 117.35,93.47 118.62,94.74 118.62,100.2 124.97,106.55 148.34,106.55 152.27,102.62 152.27,99.95
VSYS_5V0 on L14-SIGNAL: 95.76,107.57 95.76,117.47 92.46,120.78 92.46,124.21 91.44,125.22 76.45,125.22 72.14,129.54 68.58,129.54 67.31,130.81 61.47,130.81 50.29,141.99 42.29,141.99 40.77,143.51 40.77,147.32 40.01,148.08 38.23,148.08 37.08,146.94 37.08,139.7 39.88,136.91 41.53,136.91 47.62,130.81 47.62,120.65 49.53,118.75 82.55,118.75 84.33,116.97 84.33,112.39 89.66,107.06 95.25,107.06
VSYS_5V0 on L14-SIGNAL: 151.13,98.3 169.04,98.3 176.15,91.19 197.99,91.19 203.71,85.47 203.71,78.49 200.41,75.18 182.75,75.18 181.48,73.91 181.48,72.9 182.37,72.01 184.53,72.01 185.42,71.12 205.74,71.12 206.76,70.1 206.76,68.45 205.36,67.06 193.29,67.06 190.63,64.39 188.09,64.39 187.58,63.88 187.58,61.85 188.21,61.21 203.33,61.21 211.96,52.58 211.96,35.43 207.39,30.86 187.58,30.86 185.67,32.77 177.93,32.77 177.55,32.38 177.55,29.59 182.75,24.38 216.03,24.38 219.96,28.32 219.96,174.75 216.15,178.56 212.47,178.56 210.19,176.28 210.19,169.67 208.53,168.02 208.53,112.14 200.15,103.76 151.64,103.76 150.24,102.36 150.24,99.19
VSYS_5V0_APM on TOP: 182.37,108.33 190.75,108.33 191.26,107.82 191.26,103.76 190.25,102.74 190.25,91.82 189.74,91.31 182.75,91.31 182.25,91.82 182.25,96.52 180.09,98.68 180.09,100.84 180.85,101.6 181.1,101.6 181.36,101.85 181.36,102.62 180.09,103.89 180.09,106.17 180.59,106.68 181.61,106.68 181.99,107.06 181.99,107.95
VSYS_5V0_APM on BOTTOM: 182.37,108.33 194.31,108.33 194.82,107.82 194.82,92.08 194.06,91.31 184.4,91.31 183.9,91.82 183.9,96.65 182.37,98.17 180.59,98.17 180.09,98.68 180.09,105.66 181.99,107.57 181.99,107.95
VSYS_5V0_APM on L3-SIGNAL: 182.37,108.33 194.06,108.33 194.56,107.82 194.56,91.82 194.06,91.31 184.4,91.31 183.9,91.82 183.9,96.65 182.37,98.17 180.59,98.17 180.09,98.68 180.09,106.17 180.59,106.68 181.61,106.68 181.99,107.06 181.99,107.95
VSYS_5V0_APM on L12-SIGNAL: 188.21,111.51 185.93,113.79 179.83,113.79 178.12,112.08 178.12,96.96 180.09,95 180.09,91.69 185.93,91.69 188.21,93.98
VSYS_12V0 on TOP: 211.46,145.16 211.46,141.86 210.82,141.22 208.53,141.22 208.53,144.53 209.17,145.16
VSYS_12V0 on TOP: 1.27,170.31 4.83,170.31 5.33,170.81 5.33,173.61 5.84,174.12 13.21,174.12 13.59,174.5 13.59,176.4 13.21,176.78 2.16,176.78 1.02,175.77 1.02,170.56
VSYS_12V0 on TOP: 187.32,135 188.34,136.02 188.34,143.38 185.04,143.38 181.61,146.81 164.72,146.81 163.83,145.92 163.83,135
VSYS_12V0 on TOP: 178.69,118.75 179.58,118.75 179.58,119.89 179.32,120.14 178.94,120.14 178.69,119.89
VSYS_12V0 on BOTTOM: 171.07,135 171.07,135.51 174.37,135.51 174.88,135 175.64,135 176.15,135.51 179.45,135.51 179.96,135 185.04,135 186.06,136.02 186.06,142.75 182.63,146.18 164.72,146.18 163.96,145.41 163.96,135
VSYS_12V0 on L7-SIGNAL: 88.65,106.55 89.79,106.55 91.19,107.95 91.19,139.19 97.03,145.03 112.65,145.03 113.67,146.05 124.08,146.05 125.09,145.03 147.57,145.03 159.13,133.48 174.5,133.48 176.02,131.95 176.02,121.03 178.31,118.75 220.09,118.75 220.09,176.28 217.93,178.44 197.49,178.44 194.69,175.64 194.69,163.7 192.72,161.73 175.58,161.73 157.73,179.58 0.64,179.58 0.64,10.92 46.99,10.92 49.34,13.27 49.34,28.26 49.4,28.32 48.13,29.59 25.4,29.59 20.45,24.64 16.76,24.64 15.37,26.04 15.37,67.06 20.19,71.88 20.19,98.55 10.41,108.33 10.41,111.63 10.92,112.14 11.94,112.14 14.48,114.68 14.48,127.38 20.7,133.6 81.79,133.6 87.25,128.14 87.25,107.95
VSYS_12V0 on L12-SIGNAL: 186.06,135 187.58,136.53 187.58,147.7 185.29,149.99 165.74,149.99 163.7,147.96 163.7,135
VSYS_12V0_APM on TOP: 189.23,150.62 185.42,146.81 185.42,143.76 185.55,143.64 188.72,143.64 188.72,141.99 196.34,141.99 198.5,144.15 198.5,148.08 199.52,149.1 199.52,150.75 199.14,151.13 194.31,151.13 193.8,150.62
VTT on TOP: 138.48,16.26 138.46,16.23 139.06,15.62 141.27,15.62 141.4,15.75 141.4,25.91 139.62,27.69 138.43,27.69 138.18,27.43 138.18,25.65 138.48,25.35
VTT on TOP: 98.22,24.64 98.22,15.75 98.2,15.72 98.81,15.11 101.02,15.11 101.14,15.24 101.14,25.78 100.76,26.16 98.3,26.16 97.92,25.78 97.92,24.94
VTT on BOTTOM: 143.38,30.23 143.89,29.72 145.67,29.72 145.67,33.53 145.54,33.66 144.27,33.66 143.38,32.77
VTT on BOTTOM: 97.97,25.53 97.97,15.62 98.55,15.04 98.55,14.99 100.76,14.99 101.14,15.37 101.14,25.65 98.09,25.65
VTT on BOTTOM: 138.23,16.13 138.81,15.54 138.81,15.49 141.02,15.49 141.4,15.88 141.4,26.16 140.64,26.92 138.43,26.92 138.23,26.72
VTT on L12-SIGNAL: 96.77,25.65 96.77,14.73 99.25,12.26 143.83,12.26 145.8,14.22 145.8,31.24 144.53,32.51 140.97,32.51 138.3,29.84 138.3,16.64 136.91,15.24 102.62,15.24 100.84,17.02 100.84,25.53 100.08,26.29 97.41,26.29
N16769518 on TOP: 170.56,113.16 172.21,113.16 172.21,112.9 170.05,112.9 168.91,111.76 161.04,111.76 157.48,115.32 157.48,120.9 166.88,120.9 166.88,116.08 169.16,113.79 170.31,113.79 170.31,113.41
N16769518 on L3-SIGNAL: 170.31,112.9 170.05,112.9 168.91,111.76 161.04,111.76 157.48,115.32 157.48,120.9 166.88,120.9 166.88,116.08 169.16,113.79 170.31,113.79
N16769982 on TOP: 170.94,118.75 171.83,118.75 171.83,119.89 171.58,120.14 171.2,120.14 170.94,119.89
N16770544 on TOP: 179.83,113.16 178.31,113.16 178.31,112.9 179.96,112.9 180.21,112.65 180.85,112.65 182.12,111.38 182.12,109.73 193.55,109.73 194.31,110.49 194.31,119.89 183.39,119.89 183.39,115.82 181.36,113.79 180.09,113.79 180.09,113.41
N16770544 on L3-SIGNAL: 180.85,112.65 182.12,111.38 182.12,109.73 193.55,109.73 194.31,110.49 194.31,119.89 183.39,119.89 183.39,115.82 181.36,113.79 180.09,113.79 180.09,112.65
N16772555 on TOP: 173.99,162.69 175.13,163.83 192.53,163.83 193.29,163.07 193.29,158.62 190.75,156.08 174.62,156.08 173.99,156.72
N16772555 on BOTTOM: 188.09,158.12 188.09,163.83 183.9,163.83 183.9,158.12
N16772927 on BOTTOM: 200.41,163.96 190.88,163.96 190.75,163.83 190.75,158.12 198.63,158.12 200.41,159.89
N16828309 on TOP: 19.68,165.35 18.67,165.35 17.14,166.88 17.14,169.67 17.53,170.05 17.53,172.85 17.65,172.97 21.72,172.97 21.97,172.72 21.97,171.96 22.73,171.2 23.75,171.2 24,170.94 24,169.42 22.48,167.89 21.21,167.89 20.7,167.39 20.07,167.39 20.07,165.74
N16828490 on TOP: 34.8,161.8 31.11,161.8 30.61,162.31 30.61,165.35 31.37,166.12 31.37,167.64 31.88,168.15 34.04,168.15 34.67,167.51 34.67,164.97 35.56,164.08 37.59,164.08 37.85,163.83 37.85,162.31 37.08,161.54 35.05,161.54
N17039732 on BOTTOM: 82.93,162.94 82.68,162.94 82.68,161.54 82.55,161.42 82.55,157.86 82.68,157.73 84.58,157.73 84.96,158.12 84.96,160.27 83.95,161.29 83.57,161.29 82.93,161.93
N17040452 on BOTTOM: 78.11,148.34 77.85,148.34 77.85,146.94 77.72,146.81 77.72,143.26 77.85,143.13 79.76,143.13 80.14,143.51 80.14,145.67 79.12,146.69 78.74,146.69 78.11,147.32
N17140327 on BOTTOM: 30.86,103.5 31.11,103.5 31.11,104.9 31.24,105.03 31.24,108.58 31.11,108.71 29.21,108.71 28.83,108.33 28.83,106.17 29.84,105.16 30.23,105.16 30.86,104.52
N17515522 on BOTTOM: 148.46,100.58 148.46,101.73 148.97,102.23 150.11,102.23 150.5,101.85 150.5,100.33 150.11,99.95 149.48,99.95 148.84,100.58
N20753966 on L3-SIGNAL: 172.09,169.42 172.09,166.24 170.56,164.72 162.94,164.72 161.93,165.74 161.93,167.13 162.94,168.15 167.39,168.15 169.16,169.93 171.58,169.93
N20753978 on TOP: 167.51,173.48 167.51,170.94 167.13,170.56 167.13,169.04 168.15,168.02 169.16,168.02 169.42,168.28 169.42,170.81 169.29,170.94 169.29,173.1 168.91,173.48

Small or netless copper shapes (teardrops, artwork), in the pictures only: 7 on TOP

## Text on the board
BOTTOM: LOGIC 518452 REV C | PWB 518451 REV C | LAYER 16 | SOLDER
Ref Des/Assembly Bottom: 1
Board Geometry/Soldermask Bottom: SMS
Ref Des/Silkscreen Bottom: 39 | 1 | 2 | 119 | 120 | 40 | RoHS EXEMPT | NOT FCC APPROVED FOR RESALE | FOR EVALUATION ONLY; | GND | CSI2 CAMERA | EXPANSION | LCD | INTERFACE | DARA | BSLK
User.Comments: PWB 518451 REV C
Board Geometry/Outline: 9-7-17 | BREAK OFF TAB
TOP: COMPONENT | LAYER 1
Ref Des/Assembly Top: CONN.CABLE
Board Geometry/Soldermask Top: SMC
Ref Des/Silkscreen Top: 1 | A1 | GND | SYSBOOT | [0-15] | PGD_STAGE1 | 3V3_5V0 | PGD_UV_DETECT | B1 | DRA76xP/DRA77xP/TDA2Px-ACD EVM CPU BOARD | HDMI/LVDS OUT | USB1 | HDMI | OUT | FUSION POWER | CSI2 CAMERA | USB-ID | TOUCH | PCIe CONNECTOR | LEOPARD IMAGING | ETHERNET 0 | ETHERNET 1 | RSTOUTn | MICRO-SD | MIPI-60 | AUDIO | PWR ON | AREA | PORz | CAN2 | CYCLE | PWR | RESETn | CAN1 | PB/WAKE | USER | LEDS | 12V FAN | SATA | 12V | DAUGHTER CARD | CONN1 | USB2 | DAUGHTER | CARD | CONN3 | FPD-LINK | MIC IN | TERMINAL | LINE IN | LINE OUT | 12VDC | POWER | DCAN2 | PWR-RESET | HEADPHONE | CPU-RESET | DCAN1 | CONSOLE | USERCONFIG | POWER MEASURE | MLB/MLBP | COM MODULE | ASSY 518450 REV | S/N | TSLK
L2-GND1: LAYER 2 | GROUND
L3-SIGNAL: LAYER 3 | SIGNAL
L4-GND2: LAYER 4 | GROUND
L5-SIGNAL: LAYER 5 | SIGNAL
L6-GND3: LAYER 6 | GROUND
L7-SIGNAL: LAYER 7 | SIGNAL
L8-PWR1: LAYER 8 | POWER
L9-PWR2: LAYER 9 | POWER
L10-SIGNAL: LAYER 10 | SIGNAL
L11-GND4: LAYER 11 | GROUND
L12-SIGNAL: LAYER 12 | SIGNAL
L13-GND5: LAYER 13 | GROUND
L14-SIGNAL: LAYER 14 | SIGNAL
L15-GND6: LAYER 15 | GROUND
USER_PART_NUM_BOTTOM: BSLKC
USER_PART_NUM_TOP: TSLKC
DISPLAY_BOTTOM: SPS
DISPLAY_TOP: SPC
BODY_CENTER: CHECK PLOT ONLY
User.8: 2 | 1
User.11: SH2 | SH1 | SH6 | SH5 | SH4 | SH3 | AM/FM4 | J9 | DAB4 | J8 | DAB3 | J7 | AM/FM3 | J6 | AM/FM2 | J5 | DAB2 | J4 | DAB1 | J3 | J2 | J1 | FPD LINK IN | 1 | SW1 | 2 | 41 | 42 | 79 | 80 | 119 | 120 | P11 | LINE OUT3 | P10 | LINE OUT2 | P9 | LINE OUT1 | P8 | MIC2 | P7 | MIC1 | P6 | J16 | P1 | P5 | P2 | J10 | VIN1 | J14 | CDM | P4 | J17 | J11 | VIN2 | J12 | VIN3 | J13 | VIN4 | J15 | P3 | EXP_P3 | EXP_P2 | EXP_P1
User.12: D14 | J1 | R122 | L44 | L50 | L41 | D8 | R124 | L39 | C221 | C223 | C149 | Cbst1 | C220 | C222 | C59 | C60 | C4 | C3 | C54 | C55 | C50 | C49 | D4 | C179 | C2 | C58 | C152 | C53 | C48 | L48 | L43 | L40 | C153 | L38 | R93 | R82 | C131 | C9 | C28 | R84 | C154 | R77 | R78 | C29 | C8 | C10 | L3 | C81 | C14 | C69 | C219 | C119 | C217 | C216 | C82 | C83 | C71 | C130 | C22 | C218 | C5 | C15 | C23 | C70 | C13 | C66 | R31 | C44 | C45 | C39 | C38 | L33 | L37 | L31 | R92 | L29 | C109 | C76 | R252 | Y1 | C89 | L13 | C88 | R230 | C203 | R235 | R240 | R245 | C94 | C77 | C78 | C92 | C93 | C79 | C91 | C90 | C201 | C200 | C202 | R243 | R233 | R238 | R228 | L32 | L36 | L30 | L28 | R62 | R232 | R237 | R247 | R242 | C286 | C256 | C271 | R244 | R239 | R229 | C199 | R234 | C196 | U16 | U22 | C197 | U23 | U26 | C198 | U25 | R231 | R236 | U24 | C259 | R241 | U20 | R246 | U18 | C295 | C250 | C265 | C244 | L47 | C280 | C274 | C289 | L68 | L54 | L61 | R185 | R184 | R226 | R227 | R212 | R213 | R198 | R199 | D3 | C182 | L35 | C30 | C34 | C18 | L34 | C33 | C24 | C32 | C17 | C16 | C31 | C105 | C106 | C99 | C43 | C37 | C104 | C98 | R251 | C97 | R33 | C75 | R32 | C74 | L27 | C296 | C300 | C304 | C308 | C301 | C305 | C309 | C297 | C302 | C306 | C310 | C298 | L26 | C303 | C307 | C311 | C299 | C241 | C279 | C249 | C264 | C294 | C275 | C245 | C260 | C290 | R20 | R19 | R18 | R17 | R16 | R15 | R14 | R12 | R13 | R11 | R10 | R48 | R9 | R8 | R47 | R7 | R6 | R5 | R4 | R3 | R2 | R1 | U8 | R74 | R73 | R75 | C148 | R76 | R79 | C151 | C150 | R83 | R80 | R81 | C120 | C121 | C65 | C64 | C63 | C114 | C115 | C116 | C111 | C110
User.14: Y1 | C107 | R92 | R100 | R106 | C85 | R99 | C34 | C35 | C86 | R98 | C87 | R97 | D3 | R103 | L23 | L21 | C56 | TP26 | TP29 | C112 | R116 | R93 | L22 | L25 | C106 | R114 | U1 | D1 | R94 | U15 | C64 | U2 | C61 | R18 | R85 | U13 | C66 | C63 | C47 | C51 | C55 | C30 | C67 | R73 | C80 | C72 | U5 | U9 | C69 | C71 | U7 | R74 | C68 | C45 | R29 | C90 | C89 | R46 | C75 | C78 | C76 | C58 | C59 | C57 | C79 | R89 | R88 | C60 | C62 | C65 | R34 | C50 | R113 | L26 | C92 | C95 | C91 | C88 | R39 | C54 | L24 | C84 | C82 | C93 | C94 | R58 | R57 | R56 | R75 | R22 | R33 | R38 | R43 | R115 | R117 | R112 | R59 | R111 | J18
User.16: TP16 | J3 | TP17 | TP12 | TP13 | TP14 | TP18 | TP15 | TP5 | TP6 | TP10 | TP8 | J2 | 1 | TP2 | GND | LCD CONNECTOR | TP3 | TP4 | VCC_LED | TP29 | TP11 | TP9 | TP7 | TP30 | J1 | VCC | P1 | TP31 | TP24 | TP19 | TP25 | TP20 | TP26 | TP21 | TP27 | TP22 | TP28 | TP23 | ANT2 | ANT1 | ASSY 518400 REV | S/N
